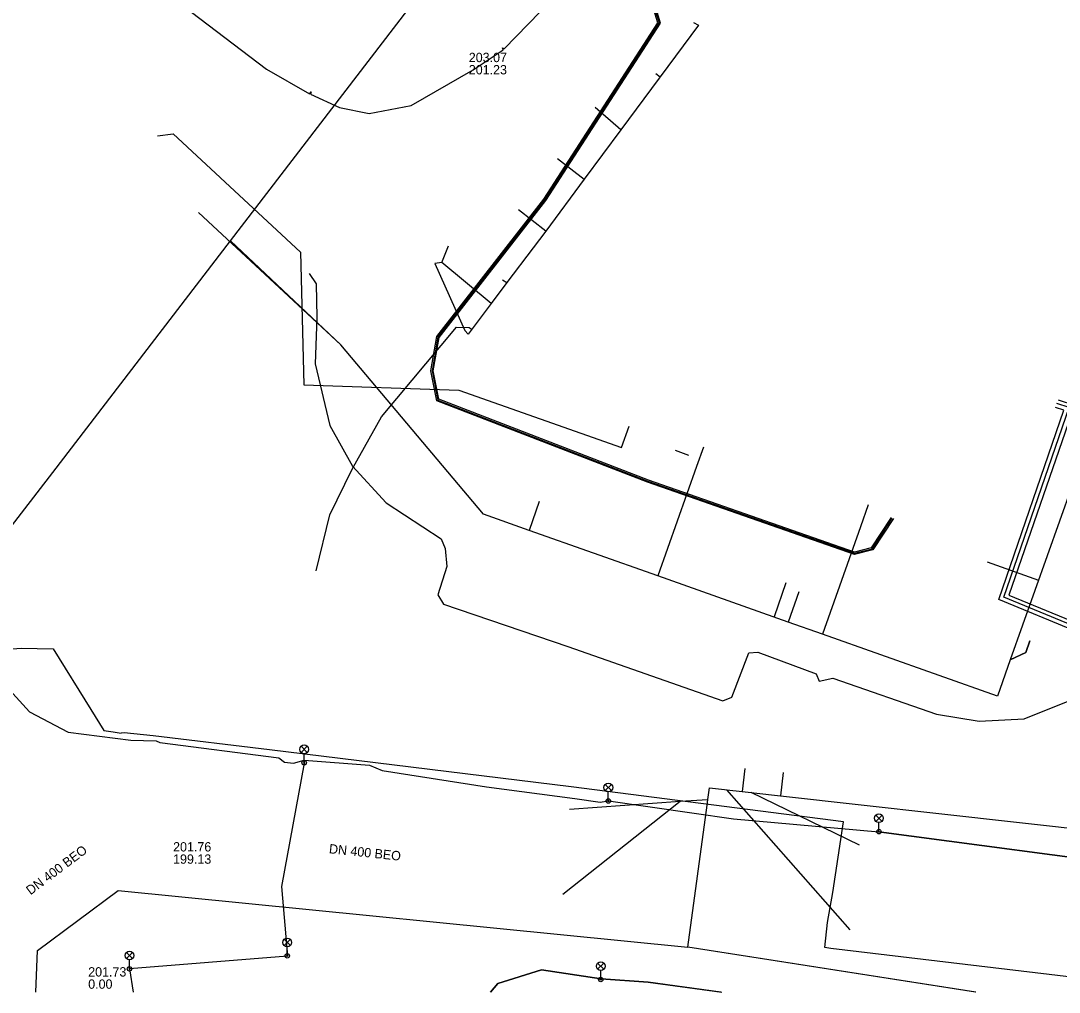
# Model space of a CAD drawing. Extents: x -598932 to -598196, y -1162210 to -1161504.
# Drawn here: x -598784.5 to -598695.5, y -1162207 to -1162123.7 of the extents above; entities that cross this region are included whole.
import ezdxf

# ---------------------------------------------------------------- set-up
doc = ezdxf.new("R2010")
doc.units = 0
for name, color, linetype in [('Vrstva 1', 7, 'Continuous'), ('Vrstva 12', 7, 'Continuous'), ('Vrstva 14', 7, 'Continuous'), ('Vrstva 19', 7, 'Continuous'), ('Vrstva 25', 7, 'Continuous'), ('Vrstva 26', 7, 'Continuous'), ('Vrstva 33', 7, 'Continuous'), ('Vrstva 4', 7, 'Continuous'), ('Vrstva 42', 7, 'Continuous'), ('Vrstva 44', 7, 'Continuous'), ('Vrstva 53', 7, 'Continuous'), ('Vrstva 55', 7, 'Continuous'), ('Vrstva 9', 7, 'Continuous')]:
    doc.layers.add(name, color=color, linetype=linetype)

msp = doc.modelspace()

# ---------------------------------------------------------------- linework, layer by layer
at = {"layer": 'Vrstva 1'}
for p, q in [((-598713.43, -1162201.62), (-598723.999, -1162189.61)), ((-598712.63, -1162194.36), (-598721.915, -1162189.849)), ((-598738.06, -1162198.55), (-598728.005, -1162190.575)), ((-598783.107, -1162203.391), (-598776.19, -1162198.24)), ((-598783.106, -1162203.388), (-598776.19, -1162198.24)), ((-598776.19, -1162198.24), (-598727.35, -1162203.11)), ((-598776.187, -1162198.238), (-598727.35, -1162203.11)), ((-598783.235, -1162206.96), (-598783.107, -1162203.391)), ((-598783.234, -1162206.96), (-598783.107, -1162203.391)), ((-598702.657, -1162206.96), (-598727.35, -1162203.11)), ((-598702.672, -1162206.96), (-598727.35, -1162203.112))]:
    msp.add_line(p, q, dxfattribs=at)
msp.add_lwpolyline([(-598737.49, -1162191.26), (-598728.005, -1162190.575), (-598725.624, -1162190.437)], dxfattribs=at)
at = {"layer": 'Vrstva 14'}
msp.add_lwpolyline([(-598772.802, -1162133.562), (-598771.478, -1162133.394), (-598760.565, -1162143.527), (-598760.275, -1162154.895), (-598746.973, -1162155.356), (-598733.018, -1162160.264), (-598732.372, -1162158.434)], dxfattribs=at)
at = {"layer": 'Vrstva 19'}
msp.add_line((-598776.62, -1162184.64), (-598775.94, -1162184.75), dxfattribs=at)
for points in [[(-598790.609, -1162178.043), (-598788.52, -1162177.775), (-598784.49, -1162177.47), (-598781.76, -1162177.54), (-598778.53, -1162182.72), (-598777.42, -1162184.54), (-598776.62, -1162184.64)], [(-598682.975, -1162206.96), (-598689.64, -1162206.25), (-598715.09, -1162203.22), (-598715.61, -1162203.12), (-598715.37, -1162200.99), (-598714.92, -1162198.4), (-598713.99, -1162192.37), (-598737.34, -1162189.37), (-598763.21, -1162186.18), (-598773.189, -1162184.991), (-598775.66, -1162184.73), (-598775.94, -1162184.75)]]:
    msp.add_lwpolyline(points, dxfattribs=at)
at = {"layer": 'Vrstva 25'}
msp.add_lwpolyline([(-598683.649, -1162183.117), (-598685.624, -1162183.497), (-598686.83, -1162178.648), (-598700.25, -1162173.116), (-598694.648, -1162156.858), (-598695.706, -1162156.517)], dxfattribs=at)
at = {"layer": 'Vrstva 26'}
for points in [[(-598695.599, -1162156.184), (-598694.201, -1162156.634), (-598699.812, -1162172.918), (-598686.533, -1162178.392), (-598685.364, -1162183.091), (-598683.715, -1162182.773)], [(-598683.583, -1162183.461), (-598685.884, -1162183.903), (-598687.127, -1162178.904), (-598700.688, -1162173.314), (-598695.095, -1162157.082), (-598695.813, -1162156.85)]]:
    msp.add_lwpolyline(points, dxfattribs=at)
at = {"layer": 'Vrstva 33'}
for p, q in [((-598760.505, -1162185.88), (-598759.975, -1162186.41)), ((-598760.505, -1162186.41), (-598759.975, -1162185.88)), ((-598760.24, -1162187.295), (-598760.24, -1162186.52)), ((-598734.427, -1162189.154), (-598733.897, -1162189.684)), ((-598734.427, -1162189.684), (-598733.897, -1162189.154)), ((-598734.162, -1162190.569), (-598734.162, -1162189.794)), ((-598711.225, -1162191.785), (-598710.695, -1162192.315)), ((-598711.225, -1162192.315), (-598710.695, -1162191.785)), ((-598710.96, -1162193.2), (-598710.96, -1162192.425)), ((-598761.955, -1162202.425), (-598761.425, -1162202.955)), ((-598761.955, -1162202.955), (-598761.425, -1162202.425)), ((-598761.69, -1162203.84), (-598761.69, -1162203.065)), ((-598775.485, -1162203.545), (-598774.955, -1162204.075)), ((-598775.485, -1162204.075), (-598774.955, -1162203.545)), ((-598775.22, -1162204.96), (-598775.22, -1162204.185)), ((-598735.077, -1162204.457), (-598734.547, -1162204.987)), ((-598735.077, -1162204.987), (-598734.547, -1162204.457)), ((-598734.812, -1162205.872), (-598734.812, -1162205.097))]:
    msp.add_line(p, q, dxfattribs=at)
for centre, radius in [((-598760.24, -1162186.145), 0.375), ((-598760.24, -1162187.295), 0.19), ((-598760.24, -1162187.295), 0.05), ((-598734.162, -1162189.419), 0.375), ((-598734.162, -1162190.569), 0.19), ((-598734.162, -1162190.569), 0.05), ((-598710.96, -1162192.05), 0.375), ((-598710.96, -1162193.2), 0.19), ((-598710.96, -1162193.2), 0.05), ((-598761.69, -1162202.69), 0.375), ((-598775.22, -1162203.81), 0.375), ((-598761.69, -1162203.84), 0.19), ((-598761.69, -1162203.84), 0.05), ((-598734.812, -1162204.722), 0.375), ((-598775.22, -1162204.96), 0.19), ((-598775.22, -1162204.96), 0.05), ((-598734.812, -1162205.872), 0.19), ((-598734.812, -1162205.872), 0.05)]:
    msp.add_circle(centre, radius, dxfattribs=at)
at = {"layer": 'Vrstva 42'}
msp.add_lwpolyline([(-598747.47, -1162100.12), (-598746.85, -1162100.55), (-598730.16, -1162122.72), (-598729.81, -1162123.89), (-598739.6, -1162139.04), (-598748.77, -1162150.8), (-598749.27, -1162153.71), (-598748.78, -1162156.21), (-598730.76, -1162163.16), (-598713.05, -1162169.34), (-598711.55, -1162168.95), (-598709.81, -1162166.32)], dxfattribs=at)
at = {"layer": 'Vrstva 44'}
for points in [[(-598709.907, -1162166.286), (-598711.612, -1162168.863), (-598713.046, -1162169.236), (-598730.726, -1162163.066), (-598748.692, -1162156.137), (-598749.168, -1162153.709), (-598748.676, -1162150.842), (-598739.518, -1162139.098), (-598729.701, -1162123.906), (-598730.069, -1162122.674), (-598746.78, -1162100.477), (-598747.49, -1162099.984), (-598747.586, -1162099.34), (-598746.567, -1162097.567)], [(-598709.713, -1162166.354), (-598711.488, -1162169.037), (-598713.054, -1162169.444), (-598730.794, -1162163.254), (-598748.868, -1162156.283), (-598749.372, -1162153.711), (-598748.864, -1162150.758), (-598739.682, -1162138.982), (-598729.919, -1162123.874), (-598730.251, -1162122.766), (-598746.92, -1162100.623), (-598748.006, -1162099.869), (-598749.344, -1162099.354), (-598751.274, -1162098.107)]]:
    msp.add_lwpolyline(points, dxfattribs=at)
at = {"layer": 'Vrstva 53'}
msp.add_lwpolyline([(-598759.22, -1162170.85), (-598758.05, -1162166.05), (-598756.13, -1162162.12), (-598753.6, -1162157.64), (-598747.18, -1162149.95), (-598746.09, -1162149.98), (-598745.83, -1162150.17)], dxfattribs=at)
at = {"layer": 'Vrstva 55'}
for p, q in [((-598730.09, -1162128.21), (-598729.71, -1162128.5)), ((-598733.1, -1162133.06), (-598735.3, -1162131.13)), ((-598738.51, -1162135.5), (-598736.22, -1162137.27)), ((-598739.53, -1162141.73), (-598741.85, -1162139.92)), ((-598748.44, -1162144.43), (-598747.86, -1162142.99)), ((-598743.24, -1162145.91), (-598742.87, -1162146.13))]:
    msp.add_line(p, q, dxfattribs=at)
for points in [[(-598774.34, -1162119.71), (-598771.33, -1162121.84), (-598763.47, -1162127.84), (-598759.78, -1162129.96), (-598759.65, -1162129.79), (-598759.7, -1162130), (-598757.22, -1162131.13), (-598754.68, -1162131.66), (-598751.07, -1162130.96), (-598745.76, -1162127.9), (-598743.18, -1162126.18), (-598743.23, -1162126.03), (-598743.09, -1162126.11), (-598740, -1162122.94), (-598734.1, -1162115.77), (-598730.07, -1162110.44), (-598730.06, -1162110.01), (-598732.17, -1162108.4)], [(-598726.87, -1162123.84), (-598726.42, -1162124.09), (-598733.1, -1162133.06), (-598736.22, -1162137.27), (-598739.53, -1162141.73), (-598740.6, -1162143.17)], [(-598740.6, -1162143.17), (-598742.87, -1162146.13), (-598744.21, -1162147.92), (-598746.18, -1162150.55)], [(-598744.21, -1162147.92), (-598748.44, -1162144.43), (-598749.03, -1162144.5), (-598746.46, -1162150.26), (-598746.18, -1162150.55)], [(-598759.82, -1162145.36), (-598759.21, -1162146.25), (-598759.16, -1162149.12), (-598759.31, -1162153.1), (-598758.04, -1162158.38), (-598756.1, -1162161.88), (-598753.21, -1162165.02), (-598748.48, -1162168.09), (-598748.15, -1162168.93), (-598748, -1162170.47), (-598748.77, -1162172.89), (-598748.3, -1162173.71), (-598737.62, -1162177.32)], [(-598737.62, -1162177.32), (-598724.34, -1162182), (-598723.57, -1162181.68), (-598722.12, -1162177.86), (-598721.35, -1162177.83), (-598716.35, -1162179.68), (-598716.07, -1162180.29), (-598714.92, -1162180.05), (-598706.03, -1162183.12), (-598702.36, -1162183.72), (-598698.5, -1162183.52), (-598694.6, -1162181.97), (-598691.49, -1162179.83), (-598688.54, -1162175.93), (-598687.82, -1162175.47), (-598687.08, -1162175.14), (-598684.53, -1162175.94), (-598683.64, -1162175.35)], [(-598785.78, -1162180.74), (-598783.79, -1162182.93), (-598780.48, -1162184.67), (-598775.1, -1162185.36), (-598772.94, -1162185.41), (-598772.62, -1162185.56), (-598762.4, -1162186.87), (-598761.93, -1162187.25), (-598761.16, -1162187.34), (-598760.23, -1162187.07), (-598760.23, -1162187.33), (-598760.23, -1162187.07), (-598754.64, -1162187.51), (-598753.55, -1162187.95), (-598744.62, -1162189.36), (-598737.04, -1162190.35), (-598734.87, -1162190.68), (-598734.15, -1162190.57)], [(-598785.78, -1162180.74), (-598783.79, -1162182.93), (-598780.48, -1162184.67), (-598775.1, -1162185.36), (-598772.94, -1162185.41), (-598772.62, -1162185.56), (-598762.4, -1162186.87), (-598761.93, -1162187.25), (-598761.16, -1162187.34), (-598760.23, -1162187.07), (-598760.23, -1162187.33), (-598760.25, -1162187.451)], [(-598760.23, -1162187.33), (-598762.194, -1162197.903), (-598761.666, -1162203.864), (-598775.22, -1162204.96), (-598774.911, -1162206.96)], [(-598734.15, -1162190.57), (-598723.421, -1162192.088), (-598710.96, -1162193.2), (-598687.278, -1162196.351), (-598662.25, -1162199.4), (-598645.273, -1162196.322), (-598639.12, -1162193.8), (-598645.273, -1162196.322), (-598662.25, -1162199.4), (-598687.278, -1162196.351), (-598710.96, -1162193.2)], [(-598724.507, -1162206.96), (-598730.75, -1162206.09), (-598734.784, -1162205.816), (-598739.901, -1162205.038), (-598743.627, -1162206.206), (-598744.264, -1162206.96)], [(-598744.264, -1162206.96), (-598743.627, -1162206.206), (-598739.901, -1162205.038), (-598734.784, -1162205.816), (-598730.75, -1162206.09), (-598724.425, -1162206.96)]]:
    msp.add_lwpolyline(points, dxfattribs=at)
at = {"layer": 'Vrstva 9'}
for p, q in [((-598757.09, -1162151.49), (-598769.29, -1162140.13)), ((-598757.09, -1162151.49), (-598766.552, -1162142.572)), ((-598744.85, -1162165.99), (-598757.09, -1162151.49)), ((-598728.44, -1162160.512), (-598727.275, -1162160.922)), ((-598726.011, -1162160.255), (-598726.59, -1162161.89)), ((-598726.59, -1162161.89), (-598729.912, -1162171.277)), ((-598740.076, -1162164.899), (-598740.937, -1162167.375)), ((-598711.872, -1162165.192), (-598712.54, -1162167.08)), ((-598712.54, -1162167.08), (-598715.794, -1162176.273)), ((-598712.54, -1162167.08), (-598715.794, -1162176.273)), ((-598701.691, -1162170.072), (-598697.264, -1162171.634)), ((-598718.93, -1162171.86), (-598719.953, -1162174.801)), ((-598717.835, -1162172.635), (-598718.738, -1162175.232)), ((-598698.351, -1162177.837), (-598698.023, -1162176.857)), ((-598699.699, -1162178.482), (-598698.351, -1162177.837)), ((-598722.449, -1162187.775), (-598722.677, -1162189.762)), ((-598719.166, -1162188.143), (-598719.388, -1162190.131))]:
    msp.add_line(p, q, dxfattribs=at)
for points in [[(-598786.41, -1162168.23), (-598785.816, -1162167.658), (-598781.796, -1162162.423), (-598766.552, -1162142.572), (-598751.343, -1162122.767), (-598746.471, -1162116.422)], [(-598686.24, -1162140.62), (-598687.047, -1162142.889), (-598692.301, -1162157.669), (-598699.699, -1162178.482), (-598700.8, -1162181.58)], [(-598700.8, -1162181.58), (-598715.794, -1162176.273), (-598718.738, -1162175.232), (-598729.912, -1162171.277), (-598740.937, -1162167.375), (-598744.85, -1162165.99)], [(-598698.023, -1162176.857), (-598698.351, -1162177.837), (-598699.699, -1162178.482)], [(-598727.35, -1162203.11), (-598725.692, -1162190.936), (-598725.624, -1162190.437), (-598725.49, -1162189.45)], [(-598725.49, -1162189.45), (-598724.197, -1162189.589), (-598723.999, -1162189.61), (-598722.677, -1162189.762), (-598721.915, -1162189.849), (-598721.674, -1162189.876), (-598719.388, -1162190.131), (-598657.924, -1162196.995)]]:
    msp.add_lwpolyline(points, dxfattribs=at)

# ---------------------------------------------------------------- texts
at = {"layer": 'Vrstva 12'}
for s, p in [('203.07', (-598746.124, -1162127.247)), ('201.23', (-598746.124, -1162128.297))]:
    msp.add_text(s, height=0.8, dxfattribs=at).set_placement(p)
at = {"layer": 'Vrstva 4'}
for rotation, p in [(37, (-598783.703, -1162198.661)), (354, (-598758.14, -1162195.045))]:
    msp.add_text('DN 400 BEO', height=0.8, rotation=rotation, dxfattribs=at).set_placement(p)
for s, p in [('201.76', (-598771.478, -1162194.899)), ('199.13', (-598771.478, -1162195.949)), ('201.73', (-598778.757, -1162205.615)), ('0.00', (-598778.757, -1162206.665))]:
    msp.add_text(s, height=0.8, dxfattribs=at).set_placement(p)

doc.saveas('drawing.dxf')
